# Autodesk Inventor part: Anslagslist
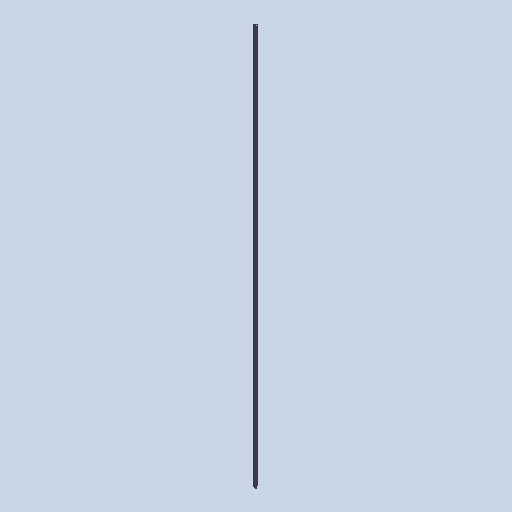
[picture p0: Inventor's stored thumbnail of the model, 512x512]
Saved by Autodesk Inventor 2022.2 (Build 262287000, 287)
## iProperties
Created: 2019-06
Part Number: Anslagslist
Material: Aluminum 6061, Welded
Document SubType Name: Modeling
Designer: cl
Density: 2.7 g/cm^3
Appearance: Weld - Aluminum
Author: cl
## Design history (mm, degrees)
sketch "Sketch1"
  geometry: L1 (0, 0)-(-19, 6.245); L2 (-19, 6.245)-(-29, 6.245); L3 (0, -3.158)-(-10, 0.129); L4 (0, 0)-(0, -3.158); L5 (-10, 0.129)-(-10, -14.871); L6 (-10, -14.871)-(-13, -14.871); L7 (-13, -14.871)-(-13, 1.115); L8 (-13, 1.115)-(-19.48, 3.245); L9 (-19.48, 3.245)-(-29, 3.245); L10 (-29, 3.245)-(-29, 6.245)
  constraints: 20 end point, 3 perpendicular, 2 horizontal, 2 parallel, 2 vertical, 1 collinear
  dimensions: "d0" = 3 distance between parallel lines of L3 L1; "d1" = 15 distance of L3.end L5.end; "d2" = 3 distance of L5.end L6.end; "d3" = 10 horizontal distance of L3.end L3.start; "d4" = 10 distance of L1.end L2.end; "d5" = 3 distance between parallel lines of L9 L2; "d6" = 20 distance of L1.start L1.end; "d8" = 29 distance between parallel lines of L10 L4
extrude "Extrusion1" new body sketch "Sketch1" distance "d11" = 2991 (computed from Daghöjd); taper "d12" = 0 deg
body "Solid1"
other parameters: "BladBredd" = 987.5, "Fönsterhöjd" = 862
